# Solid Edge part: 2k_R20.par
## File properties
Author: Türk
Template: Iso Part.par
Last saved by: Türk
Revision: 7
Application: Solid Edge
Accuracy: 0,990
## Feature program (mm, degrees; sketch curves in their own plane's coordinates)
pattern "PatternOccurrence_6"  XOffset = 14.4 deg
pattern "PatternOccurrence_7"  XCount = 25; XOffset = 14.4 deg
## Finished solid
Body 1: solid body, 153 faces, 452 edges, 300 vertices.
  Faces by surface: plane 102, cylinder 51
  Edges by curve: line 350, circle 102
Bounding box of the edges (mm): 47.887 x 30.000 x 47.968, from (-23.8867, 0, -23.9822) to (24, 30, 23.9858).
Cylindrical faces by radius (mm): R14 x1, R20 x25, R24 x25
Planar faces by outward normal: +y 1, -y 1, oblique 100
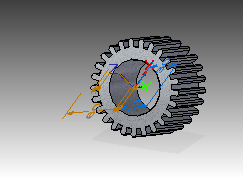
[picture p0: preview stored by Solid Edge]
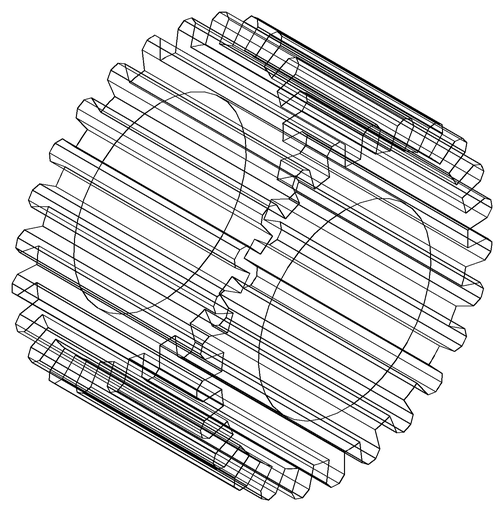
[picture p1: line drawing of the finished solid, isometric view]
